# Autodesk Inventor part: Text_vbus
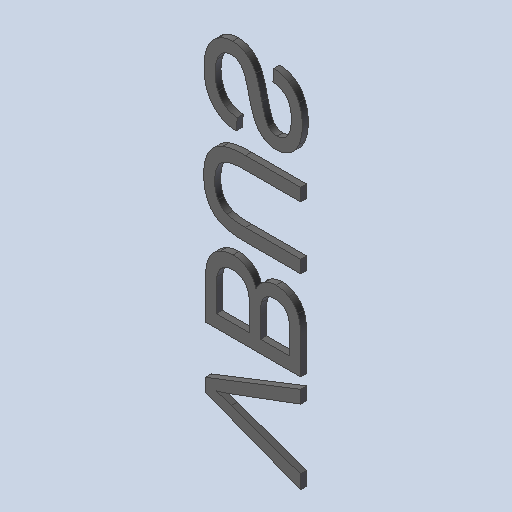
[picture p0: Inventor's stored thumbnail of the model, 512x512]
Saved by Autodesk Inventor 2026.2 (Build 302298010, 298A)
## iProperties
Created: 2026-10
Part Number: Text_vbus
Material: Générique
Document SubType Name: Modeling
Designer: mel
Density: 1 g/cm^3
Appearance: Par défaut
Author: mel
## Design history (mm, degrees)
feature "Base1"
feature "Base2"
feature "Base3"
feature "Base4"
node "Solide1"
node "Solide2"
node "Solide3"
node "Solide4"
